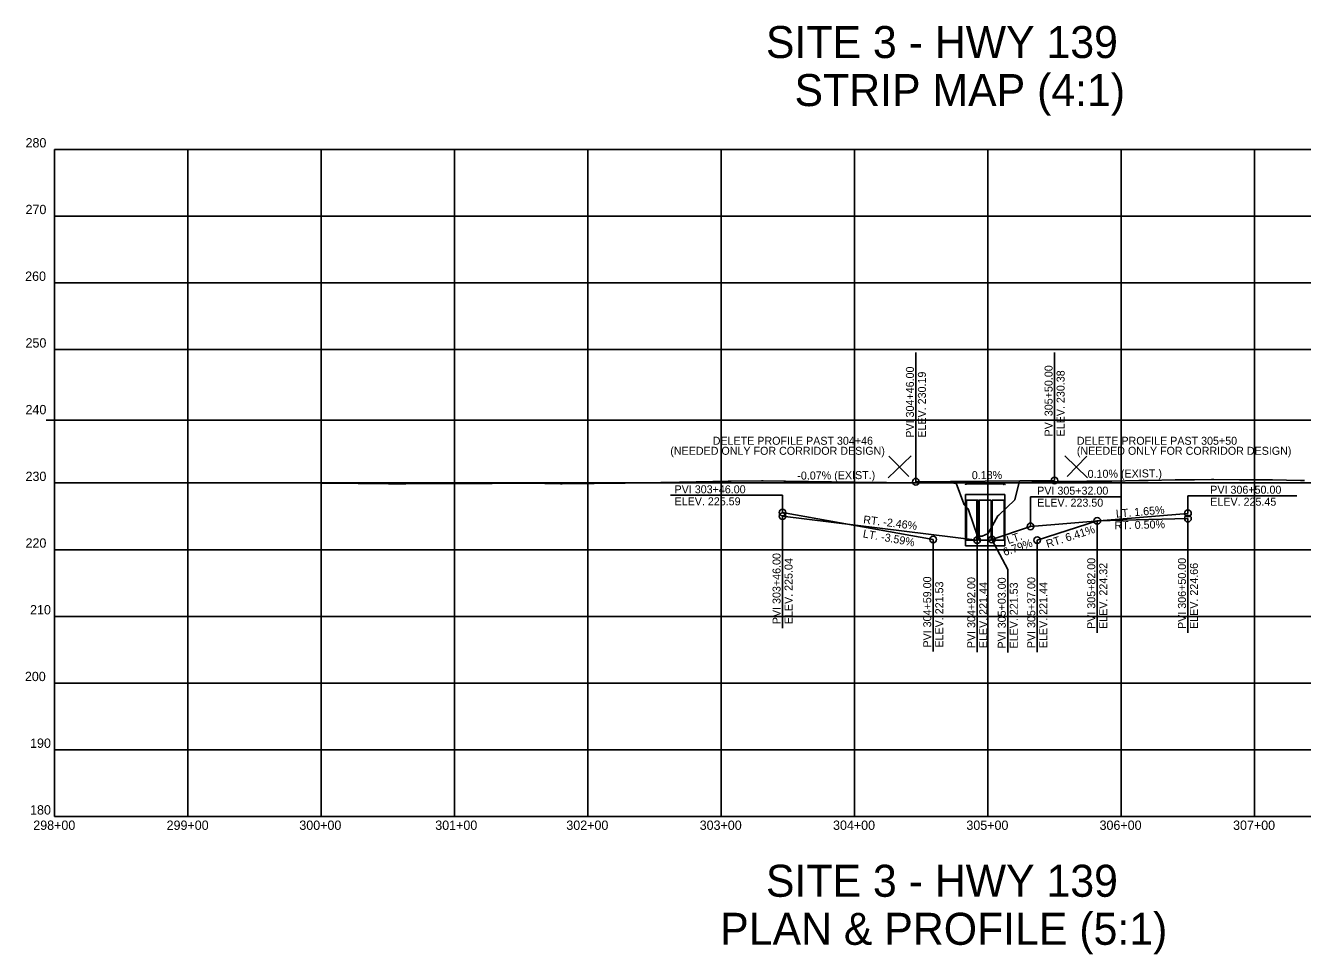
# Model space of a CAD drawing. Extents: x 1811793 to 1813336, y 532176 to 533566.
# Drawn here: x 1811793 to 1812750, y 532176 to 532872 of the extents above; entities that cross this region are included whole.
import ezdxf

# ---------------------------------------------------------------- set-up
doc = ezdxf.new("R2010")
doc.units = 0
for name, color, linetype in [('Default', 7, 'Continuous'), ('R_Axis', 7, 'Continuous'), ('R_Axis Annot', 7, 'Continuous'), ('R_Concrete', 7, 'Continuous'), ('R_Exist Surface', 7, 'Continuous'), ('R_Grid', 7, 'Continuous'), ('R_No Plot', 7, 'Continuous'), ('R_Vert Alg', 7, 'Continuous'), ('R_Vert Alg Annot', 7, 'Continuous')]:
    doc.layers.add(name, color=color, linetype=linetype)

msp = doc.modelspace()

# ---------------------------------------------------------------- linework, layer by layer
at = {"layer": 'R_Axis'}
for q in [(1811814.24, 532779.32), (1813314.24, 532279.32)]:
    msp.add_line((1811814.24, 532279.32), q, dxfattribs=at)
at = {"layer": 'R_Concrete'}
for p, q in [((1812497.49, 532520.69), (1812526.99, 532520.69)), ((1812497.49, 532520.69), (1812497.49, 532482.35)), ((1812526.99, 532520.69), (1812526.99, 532482.35)), ((1812498.07, 532516.52), (1812498.07, 532486.52)), ((1812498.07, 532516.52), (1812507.07, 532516.52)), ((1812507.07, 532516.52), (1812507.07, 532486.52)), ((1812507.74, 532516.52), (1812507.74, 532486.52)), ((1812507.74, 532516.52), (1812516.74, 532516.52)), ((1812516.74, 532516.52), (1812516.74, 532486.52)), ((1812517.41, 532516.52), (1812517.41, 532486.52)), ((1812517.41, 532516.52), (1812526.41, 532516.52)), ((1812526.41, 532516.52), (1812526.41, 532486.52)), ((1812526.99, 532482.35), (1812497.49, 532482.35)), ((1812498.07, 532486.52), (1812507.07, 532486.52)), ((1812507.74, 532486.52), (1812516.74, 532486.52)), ((1812517.41, 532486.52), (1812526.41, 532486.52))]:
    msp.add_line(p, q, dxfattribs=at)
at = {"layer": 'R_Exist Surface'}
msp.add_lwpolyline([(1812014.24, 532529.22), (1812019.25, 532529.19), (1812019.33, 532529.19), (1812042.01, 532528.95), (1812044.51, 532528.93), (1812064.7, 532528.71), (1812064.77, 532528.71), (1812067.94, 532528.73), (1812077.49, 532528.78), (1812077.61, 532528.78), (1812090.18, 532528.85), (1812090.44, 532528.85), (1812102.86, 532528.92), (1812103.27, 532528.91), (1812115.54, 532528.98), (1812116.1, 532528.98), (1812128.74, 532529.02), (1812129.34, 532529.02), (1812141.98, 532529.06), (1812142.59, 532529.06), (1812155.21, 532529.1), (1812155.83, 532529.1), (1812168.45, 532529.14), (1812169.08, 532529.14), (1812170.25, 532529.13), (1812193.8, 532528.65), (1812194.98, 532528.65), (1812218.06, 532528.96), (1812219.02, 532528.96), (1812242.33, 532529.27), (1812255.25, 532529.52), (1812256.1, 532529.54), (1812268.98, 532529.79), (1812270.02, 532529.81), (1812282.86, 532530.06), (1812295.48, 532530.3), (1812296.43, 532530.31), (1812319.51, 532530.57), (1812320.55, 532530.58), (1812321.6, 532530.58), (1812344.55, 532530.85), (1812345.68, 532530.85), (1812361.12, 532530.62), (1812362.56, 532530.64), (1812377.89, 532530.41), (1812379.44, 532530.44), (1812379.61, 532530.43), (1812395.02, 532530.2), (1812397.05, 532530.17), (1812412.41, 532529.94), (1812412.79, 532529.92), (1812414.14, 532529.92), (1812425.52, 532529.8), (1812436.77, 532529.68), (1812438.25, 532529.67), (1812449.46, 532529.56), (1812450.99, 532529.55), (1812462.15, 532529.44), (1812463.73, 532529.43), (1812475.43, 532529.35), (1812477.1, 532529.37), (1812488.78, 532529.29), (1812490.48, 532529.3), (1812496.11, 532513.76), (1812496.25, 532513.18), (1812496.3, 532513.09), (1812499.47, 532509.86), (1812499.87, 532508.55), (1812506.35, 532489.48), (1812506.43, 532489.5), (1812509.62, 532489.49), (1812509.87, 532489.58), (1812514.33, 532491.59), (1812514.89, 532492.42), (1812521.66, 532504.6), (1812522.52, 532505.18), (1812534.38, 532516.81), (1812534.68, 532518.04), (1812537.66, 532529.71), (1812540.31, 532529.66), (1812553.71, 532530.08), (1812567.1, 532530.49), (1812569.75, 532530.45), (1812585.41, 532530.55), (1812588.41, 532530.62), (1812604.07, 532530.73), (1812607.07, 532530.8), (1812627.3, 532531.15), (1812630.89, 532531.23), (1812634.37, 532531.31), (1812654.72, 532531.66), (1812656.84, 532531.66), (1812669.17, 532531.75), (1812681.94, 532531.85), (1812683.6, 532531.85), (1812702.91, 532531.74), (1812705.62, 532531.75), (1812724.71, 532531.64), (1812727.63, 532531.65), (1812748.61, 532531.26), (1812751.74, 532531.2)], dxfattribs=at)
at = {"layer": 'R_Grid'}
for p, q in [((1811814.24, 532779.32), (1813314.24, 532779.32)), ((1811814.24, 532779.32), (1813314.24, 532779.32)), ((1811914.24, 532279.32), (1811914.24, 532779.32)), ((1812014.24, 532279.32), (1812014.24, 532779.32)), ((1812114.24, 532279.32), (1812114.24, 532779.32)), ((1812214.24, 532279.32), (1812214.24, 532779.32)), ((1812314.24, 532279.32), (1812314.24, 532779.32)), ((1812414.24, 532279.32), (1812414.24, 532779.32)), ((1812514.24, 532279.32), (1812514.24, 532779.32)), ((1812614.24, 532279.32), (1812614.24, 532779.32)), ((1812714.24, 532279.32), (1812714.24, 532779.32)), ((1811814.24, 532729.32), (1813314.24, 532729.32)), ((1811814.24, 532679.32), (1813314.24, 532679.32)), ((1811814.24, 532629.32), (1813314.24, 532629.32)), ((1811808, 532576.42), (1813308, 532576.42)), ((1811814.24, 532529.32), (1813314.24, 532529.32)), ((1811814.24, 532479.32), (1813314.24, 532479.32)), ((1811814.24, 532429.32), (1813314.24, 532429.32)), ((1811814.24, 532379.32), (1813314.24, 532379.32)), ((1811814.24, 532329.32), (1813314.24, 532329.32))]:
    msp.add_line(p, q, dxfattribs=at)
at = {"layer": 'R_No Plot'}
for p, q in [((1812456.63, 532549.61), (1812439.53, 532533.27)), ((1812439.96, 532549.35), (1812454.83, 532534.3)), ((1812571.85, 532549.61), (1812588.94, 532533.27)), ((1812588.51, 532549.35), (1812573.64, 532534.3)), ((1812497.81, 532528.73), (1812526.6, 532528.64)), ((1812505.91, 532516.52), (1812505.91, 532486.52))]:
    msp.add_line(p, q, dxfattribs=at)
for points in [[(1812497.84, 532528.77), (1812497.34, 532529.27), (1812497.84, 532528.77), (1812497.34, 532528.27), (1812497.84, 532528.77), (1812498.34, 532528.27), (1812497.84, 532528.77), (1812498.34, 532529.27)], [(1812526.64, 532528.67), (1812526.14, 532529.17), (1812526.64, 532528.67), (1812526.14, 532528.17), (1812526.64, 532528.67), (1812527.14, 532528.17), (1812526.64, 532528.67), (1812527.14, 532529.17)]]:
    msp.add_lwpolyline(points, dxfattribs=at)
at = {"layer": 'R_Vert Alg'}
for p, q in [((1812460.24, 532530.29), (1812564.24, 532531.24)), ((1812360.24, 532504.5), (1812506.24, 532486.52)), ((1812551.24, 532486.52), (1812596.24, 532500.94)), ((1812596.24, 532500.94), (1812664.24, 532502.64))]:
    msp.add_line(p, q, dxfattribs=at)
at = {"layer": 'R_Vert Alg Annot'}
for p, q in [((1812460.24, 532560.29), (1812460.24, 532627.21)), ((1812564.24, 532561.24), (1812564.24, 532627.21)), ((1812460.24, 532530.29), (1812460.24, 532560.29)), ((1812564.24, 532531.24), (1812564.24, 532561.24)), ((1812276.24, 532520.09), (1812360.24, 532520.09)), ((1812360.24, 532507.27), (1812360.24, 532520.09)), ((1812546.24, 532496.82), (1812546.24, 532519.07)), ((1812546.24, 532519.07), (1812614.14, 532519.07)), ((1812664.24, 532506.58), (1812664.24, 532519.79)), ((1812664.24, 532519.79), (1812746, 532519.79)), ((1812360.24, 532507.27), (1812473.24, 532486.97)), ((1812360.24, 532420.5), (1812360.24, 532504.5)), ((1812546.24, 532496.82), (1812664.24, 532506.58)), ((1812596.24, 532416.94), (1812596.24, 532500.94)), ((1812664.24, 532416.94), (1812664.24, 532502.64)), ((1812517.24, 532486.97), (1812546.24, 532496.82)), ((1812473.24, 532402.97), (1812473.24, 532486.97)), ((1812506.24, 532402.52), (1812506.24, 532486.52)), ((1812517.24, 532486.97), (1812529.12, 532464.58)), ((1812551.24, 532402.52), (1812551.24, 532486.52)), ((1812529.12, 532402.27), (1812529.12, 532464.58))]:
    msp.add_line(p, q, dxfattribs=at)
for centre in [(1812460.24, 532530.29), (1812564.24, 532531.24), (1812360.24, 532507.27), (1812664.24, 532506.58), (1812360.24, 532504.5), (1812546.24, 532496.82), (1812596.24, 532500.94), (1812664.24, 532502.64), (1812473.24, 532486.97), (1812506.24, 532486.52), (1812517.24, 532486.97), (1812551.24, 532486.52)]:
    msp.add_circle(centre, 2.5, dxfattribs=at)

# ---------------------------------------------------------------- texts
at = {"layer": 'Default'}
for s, p in [('SITE 3 - HWY 139', (1812347.77, 532847.82)), ('STRIP MAP (4:1)', (1812369.22, 532811.82)), ('SITE 3 - HWY 139', (1812347.77, 532219.19)), ('PLAN & PROFILE (5:1)', (1812313.47, 532183.19))]:
    msp.add_text(s, height=24, dxfattribs=at).set_placement(p)
at = {"layer": 'R_Axis Annot'}
for s, height, p in [('280', 7, (1811792.54, 532780.82)), ('280', 7, (1811792.54, 532780.82)), ('270', 7, (1811792.54, 532730.82)), ('260', 7, (1811792.26, 532680.82)), ('250', 7, (1811792.54, 532630.82)), ('240', 7, (1811792.54, 532580.82)), ('230', 7, (1811792.54, 532530.82)), ('220', 7, (1811792.54, 532480.82)), ('210', 7, (1811795.95, 532430.82)), ('200', 7, (1811792.07, 532380.82)), ('190', 7, (1811795.95, 532330.82)), ('180', 7, (1811795.95, 532280.82)), ('-', 0.0001, (1811814.24, 532279.32)), ('298+00', 7, (1811798.34, 532269.32)), ('299+00', 7, (1811898.34, 532269.32)), ('300+00', 7, (1811997.87, 532269.32)), ('301+00', 7, (1812099.8, 532269.32)), ('302+00', 7, (1812198.1, 532269.32)), ('303+00', 7, (1812298.1, 532269.32)), ('304+00', 7, (1812398.1, 532269.32)), ('305+00', 7, (1812498.1, 532269.32)), ('306+00', 7, (1812597.96, 532269.32)), ('307+00', 7, (1812698.1, 532269.32))]:
    msp.add_text(s, height=height, dxfattribs=at).set_placement(p)
at = {"layer": 'R_No Plot'}
for s, p in [('(NEEDED ONLY FOR CORRIDOR DESIGN)', (1812276.05, 532550.46)), ('DELETE PROFILE PAST 304+46', (1812307.85, 532557.97)), ('(NEEDED ONLY FOR CORRIDOR DESIGN)', (1812580.92, 532550.46)), ('DELETE PROFILE PAST 305+50', (1812580.92, 532557.97))]:
    msp.add_text(s, height=6, dxfattribs=at).set_placement(p)
at = {"layer": 'R_Vert Alg Annot'}
for s, rotation, p in [('PVI 304+46.00', 90, (1812458.74, 532563.29)), ('PVI 305+50.00', 90, (1812562.74, 532564.24)), ('ELEV. 230.19', 90, (1812467.74, 532563.29)), ('ELEV. 230.38', 90, (1812571.74, 532564.24)), ('-0.07% (EXIST.)', 0.5237, (1812371.33, 532531.82)), ('0.18%', 0.5237, (1812502.18, 532532.17)), ('0.10% (EXIST.)', 0.5237, (1812589.04, 532533.11)), ('LT. 1.65%', 4.7258, (1812610.44, 532503.32)), ('RT. -2.46%', 352.9782, (1812420.48, 532499.09)), ('RT. 0.50%', 1.4321, (1812609.23, 532494.5)), ('LT. -3.59%', 349.81567, (1812420.15, 532488.65)), ('LT.', 18.76032, (1812529.58, 532483.45)), ('RT. 6.41%', 17.767, (1812558.96, 532480.61)), ('6.79%', 18.76032, (1812526.73, 532474.55)), ('PVI 303+46.00', 90, (1812358.74, 532423.5)), ('ELEV. 225.04', 90, (1812367.74, 532423.5)), ('PVI 305+82.00', 90, (1812594.74, 532419.94)), ('PVI 306+50.00', 90, (1812662.74, 532419.93)), ('ELEV. 224.32', 90, (1812603.74, 532419.94)), ('ELEV. 224.66', 90, (1812671.74, 532419.93)), ('PVI 304+59.00', 90, (1812471.74, 532405.97)), ('ELEV. 221.53', 90, (1812480.74, 532405.97)), ('PVI 304+92.00', 90, (1812504.74, 532405.52)), ('ELEV. 221.44', 90, (1812513.74, 532405.52)), ('PVI 305+03.00', 90, (1812527.62, 532405.27)), ('ELEV. 221.53', 90, (1812536.62, 532405.27)), ('PVI 305+37.00', 90, (1812549.74, 532405.52)), ('ELEV. 221.44', 90, (1812558.74, 532405.52))]:
    msp.add_text(s, height=6, rotation=rotation, dxfattribs=at).set_placement(p)
for s, p in [('PVI 303+46.00', (1812279.24, 532521.59)), ('PVI 306+50.00', (1812680.98, 532521.29)), ('ELEV. 225.59', (1812279.24, 532512.59)), ('PVI 305+32.00', (1812551.2, 532520.57)), ('ELEV. 225.45', (1812680.98, 532512.29)), ('ELEV. 223.50', (1812551.2, 532511.57))]:
    msp.add_text(s, height=6, dxfattribs=at).set_placement(p)

doc.saveas('drawing.dxf')
